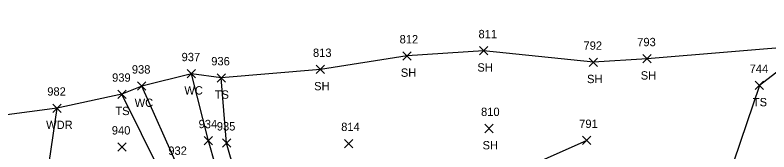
# Model space of a CAD drawing. Extents: x 1443590 to 1445966, y 578314 to 580556.
# Drawn here: x 1445312.1 to 1445493.3, y 579218.3 to 579251.1 of the extents above; entities that cross this region are included whole.
import ezdxf

# ---------------------------------------------------------------- set-up
doc = ezdxf.new("R2010")
doc.units = 0
for name, color, linetype in [('D_I', 7, 'Continuous'), ('D_TIC', 7, 'Continuous'), ('L_A', 7, 'Continuous'), ('L_I', 7, 'Continuous'), ('L_TIC', 7, 'Continuous'), ('LAWA', 7, 'Continuous'), ('LAWE', 7, 'Continuous'), ('LELB', 7, 'Continuous'), ('LSOGP', 7, 'Continuous')]:
    doc.layers.add(name, color=color, linetype=linetype)

msp = doc.modelspace()

# ---------------------------------------------------------------- linework, layer by layer
at = {"layer": 'D_TIC'}
for points in [[(1445336.84, 579218.49), (1445338.84, 579220.49)], [(1445338.84, 579218.49), (1445336.84, 579220.49)]]:
    msp.add_lwpolyline(points, dxfattribs=at)
at = {"layer": 'L_TIC'}
for points in [[(1445423.75, 579241.57), (1445425.75, 579243.57)], [(1445425.75, 579241.57), (1445423.75, 579243.57)], [(1445405.36, 579240.33), (1445407.36, 579242.33)], [(1445407.36, 579240.33), (1445405.36, 579242.33)], [(1445463.03, 579239.66), (1445465.03, 579241.66)], [(1445465.03, 579239.66), (1445463.03, 579241.66)], [(1445450.12, 579238.81), (1445452.12, 579240.81)], [(1445452.12, 579238.81), (1445450.12, 579240.81)], [(1445353.53, 579236.07), (1445355.53, 579238.07)], [(1445355.53, 579236.07), (1445353.53, 579238.07)], [(1445384.53, 579237.09), (1445386.53, 579239.09)], [(1445386.53, 579237.09), (1445384.53, 579239.09)], [(1445360.7, 579235.07), (1445362.7, 579237.07)], [(1445362.7, 579235.07), (1445360.7, 579237.07)], [(1445341.57, 579233.1), (1445343.57, 579235.1)], [(1445343.57, 579233.1), (1445341.57, 579235.1)], [(1445490.05, 579233.26), (1445492.05, 579235.26)], [(1445492.05, 579233.26), (1445490.05, 579235.26)], [(1445336.83, 579231.15), (1445338.83, 579233.15)], [(1445338.83, 579231.15), (1445336.83, 579233.15)], [(1445321.24, 579227.81), (1445323.24, 579229.81)], [(1445323.24, 579227.81), (1445321.24, 579229.81)], [(1445425.01, 579222.94), (1445427.01, 579224.94)], [(1445427.01, 579222.94), (1445425.01, 579224.94)], [(1445357.61, 579220.01), (1445359.61, 579222.01)], [(1445359.61, 579220.01), (1445357.61, 579222.01)], [(1445448.52, 579220.07), (1445450.52, 579222.07)], [(1445450.52, 579220.07), (1445448.52, 579222.07)], [(1445361.99, 579219.46), (1445363.99, 579221.46)], [(1445363.99, 579219.46), (1445361.99, 579221.46)], [(1445391.32, 579219.33), (1445393.32, 579221.33)], [(1445393.32, 579219.33), (1445391.32, 579221.33)]]:
    msp.add_lwpolyline(points, dxfattribs=at)
at = {"layer": 'LAWA'}
msp.add_lwpolyline([(1445372.27, 579155.45), (1445350.04, 579149.98), (1445331.31, 579147.35), (1445306.91, 579136.98), (1445292.9, 579134.14), (1445303.83, 579150.82), (1445315.45, 579175.06), (1445318.51, 579203.19), (1445322.24, 579228.81)], dxfattribs=at)
at = {"layer": 'LAWE'}
for points in [[(1445382.97, 579154.29), (1445380.24, 579162.28), (1445373.58, 579177.96), (1445365.33, 579197.36), (1445358.61, 579221.01), (1445354.53, 579237.07)], [(1445382.97, 579154.29), (1445384.05, 579149.01), (1445384.28, 579148.09), (1445382.5, 579147.66), (1445382.46, 579148.51), (1445377.6, 579151.89), (1445376.36, 579159.59), (1445369.12, 579176.98), (1445359.48, 579194.76), (1445353.1, 579205.3), (1445351.33, 579214.63), (1445342.57, 579234.1)]]:
    msp.add_lwpolyline(points, dxfattribs=at)
at = {"layer": 'LELB'}
for points in [[(1445527.65, 579251.11), (1445503.6, 579243.88), (1445491.05, 579234.26), (1445481.75, 579206.89), (1445483.25, 579191.2)], [(1445383.55, 579156.95), (1445381.72, 579163.83), (1445375.45, 579180.16), (1445369.1, 579199.02), (1445362.99, 579220.46), (1445361.7, 579236.07)], [(1445374.4, 579150.86), (1445374.06, 579156.47), (1445366.45, 579176.13), (1445356.62, 579193.02), (1445350.22, 579204.5), (1445347.27, 579213.15), (1445337.83, 579232.15)], [(1445449.52, 579221.07), (1445424.69, 579210.07), (1445406.41, 579188.44), (1445412.28, 579169.03)]]:
    msp.add_lwpolyline(points, dxfattribs=at)
at = {"layer": 'LSOGP'}
msp.add_lwpolyline([(1445503.6, 579243.89), (1445464.03, 579240.66), (1445451.12, 579239.81), (1445424.75, 579242.57), (1445406.35, 579241.33), (1445385.53, 579238.09), (1445361.7, 579236.08), (1445354.53, 579237.07), (1445342.57, 579234.1), (1445337.83, 579232.15), (1445322.24, 579228.8), (1445303.4, 579226.37)], dxfattribs=at)

# ---------------------------------------------------------------- texts
at = {"layer": 'D_I'}
msp.add_text('940', height=2, dxfattribs=at).set_placement((1445335.39, 579222.49))
at = {"layer": 'L_A'}
for s, p in [('SH', (1445404.85, 579236.33)), ('SH', (1445423.24, 579237.57)), ('SH', (1445449.6, 579234.81)), ('SH', (1445462.51, 579235.66)), ('SH', (1445384.02, 579233.09)), ('WC', (1445352.83, 579232.07)), ('TS', (1445360.11, 579231.07)), ('WC', (1445340.88, 579229.1)), ('TS', (1445489.45, 579229.26)), ('TS', (1445336.24, 579227.15)), ('WDR', (1445319.6, 579223.81)), ('SH', (1445424.5, 579218.94))]:
    msp.add_text(s, height=2, dxfattribs=at).set_placement(p)
at = {"layer": 'L_I'}
for s, p in [('811', (1445423.52, 579245.57)), ('812', (1445404.56, 579244.33)), ('793', (1445461.66, 579243.66)), ('792', (1445448.75, 579242.81)), ('937', (1445352.16, 579240.07)), ('813', (1445383.74, 579241.09)), ('936', (1445359.29, 579239.07)), ('938', (1445340.21, 579237.1)), ('744', (1445488.68, 579237.26)), ('939', (1445335.46, 579235.15)), ('982', (1445319.88, 579231.81)), ('810', (1445424.13, 579226.94)), ('934', (1445356.25, 579224.01)), ('935', (1445360.63, 579223.46)), ('814', (1445390.52, 579223.33)), ('791', (1445447.72, 579224.07)), ('932', (1445348.97, 579217.63))]:
    msp.add_text(s, height=2, dxfattribs=at).set_placement(p)

doc.saveas('drawing.dxf')
